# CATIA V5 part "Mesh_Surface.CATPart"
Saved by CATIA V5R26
Part number: Mesh_Surface
Bounding box of the stored display mesh (mm): x -221.31 to 305.063, y -86.794 to 148.728, z -45.705 to 27.074
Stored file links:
  D:\LinkedIn Learning\NURBS\CATIA\Class Parts\Mesh_Surface.CATPart
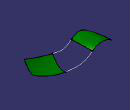
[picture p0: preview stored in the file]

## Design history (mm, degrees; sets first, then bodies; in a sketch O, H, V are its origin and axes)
AxisSystem1: origin (0, 0, 0), X (1, 0, 0), Y (0, 1, 0), Z (0, 0, 1)
Set1
  DatumSurface1
  DatumSurface2
  Connect1: Curve1 edge of DatumSurface2, Point1 vertex [face of DatumSurface2], Tension1 1, Curve2 edge of DatumSurface1, Point2 vertex [face of DatumSurface1], Tension2 1
  Connect2: Curve1 edge of DatumSurface2, Point1 vertex [face of DatumSurface2], Tension1 1, Curve2 edge of DatumSurface1, Point2 vertex [face of DatumSurface1], Tension2 1
Body1 (main body)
